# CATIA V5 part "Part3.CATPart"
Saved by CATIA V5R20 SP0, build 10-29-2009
Part number: Part3
Bounding box of the stored display mesh (mm): x 0 to 10, y -15 to 15, z -174.99 to 174.99
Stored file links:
  E:\Ehsan\Catia\Tamrin\Digital Mockup\1\Part3.CATPart
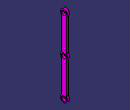
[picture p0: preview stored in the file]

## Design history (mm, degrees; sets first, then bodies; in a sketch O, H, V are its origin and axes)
Body1 (main body)
  Sketch1 on yz-plane, origin (0, 0, 0), H (0, 1, 0), V (0, 0, 1)
    arc A1 centre (0, 0) radius 15 from (-10, 11.1803) to (-10, -11.1803) ccw
    circle A2 centre (0, 0) radius 10
    arc A3 centre (0, 160) radius 15 from (10, 148.8197) to (-10, 148.8197) ccw
    circle A4 centre (0, 160) radius 10
    arc A5 centre (0, -160) radius 15 from (10, -148.8197) to (-10, -148.8197) cw
    circle A6 centre (0, -160) radius 10
    line L1 (10, 148.8197) -> (10, 11.1803)
    point P3 (10, 148.8197)
    point P4 (10, 11.1803)
    point P5 (-10, 11.1803)
    point P6 (-10, 148.8197)
    line L2 (-10, 148.8197) -> (-10, 11.1803)
    point P7 (-10, -11.1803)
    point P8 (-10, -148.8197)
    line L3 (-10, -148.8197) -> (-10, -11.1803)
    point P9 (10, -11.1803)
    point P10 (10, -148.8197)
    line L4 (10, -148.8197) -> (10, -11.1803)
    arc A7 centre (0, 0) radius 15 from (10, -11.1803) to (10, 11.1803) ccw
    radius A1 = 15
    radius A2 = 10
    distance P3 V = 10
    symmetry: A3 A5 H, A4 A6 H, P4 P5 V, P3 P6 V, L1 L2 V, P5 P7 H, P6 P8 H, L2 L3 H, P4 P9 H, P3 P10 H, L1 L4 H
    tangency: L1 A2
    coincidence: A1 A7
  Pad1: profile Sketch1, direction (1, 0, 0), length 10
